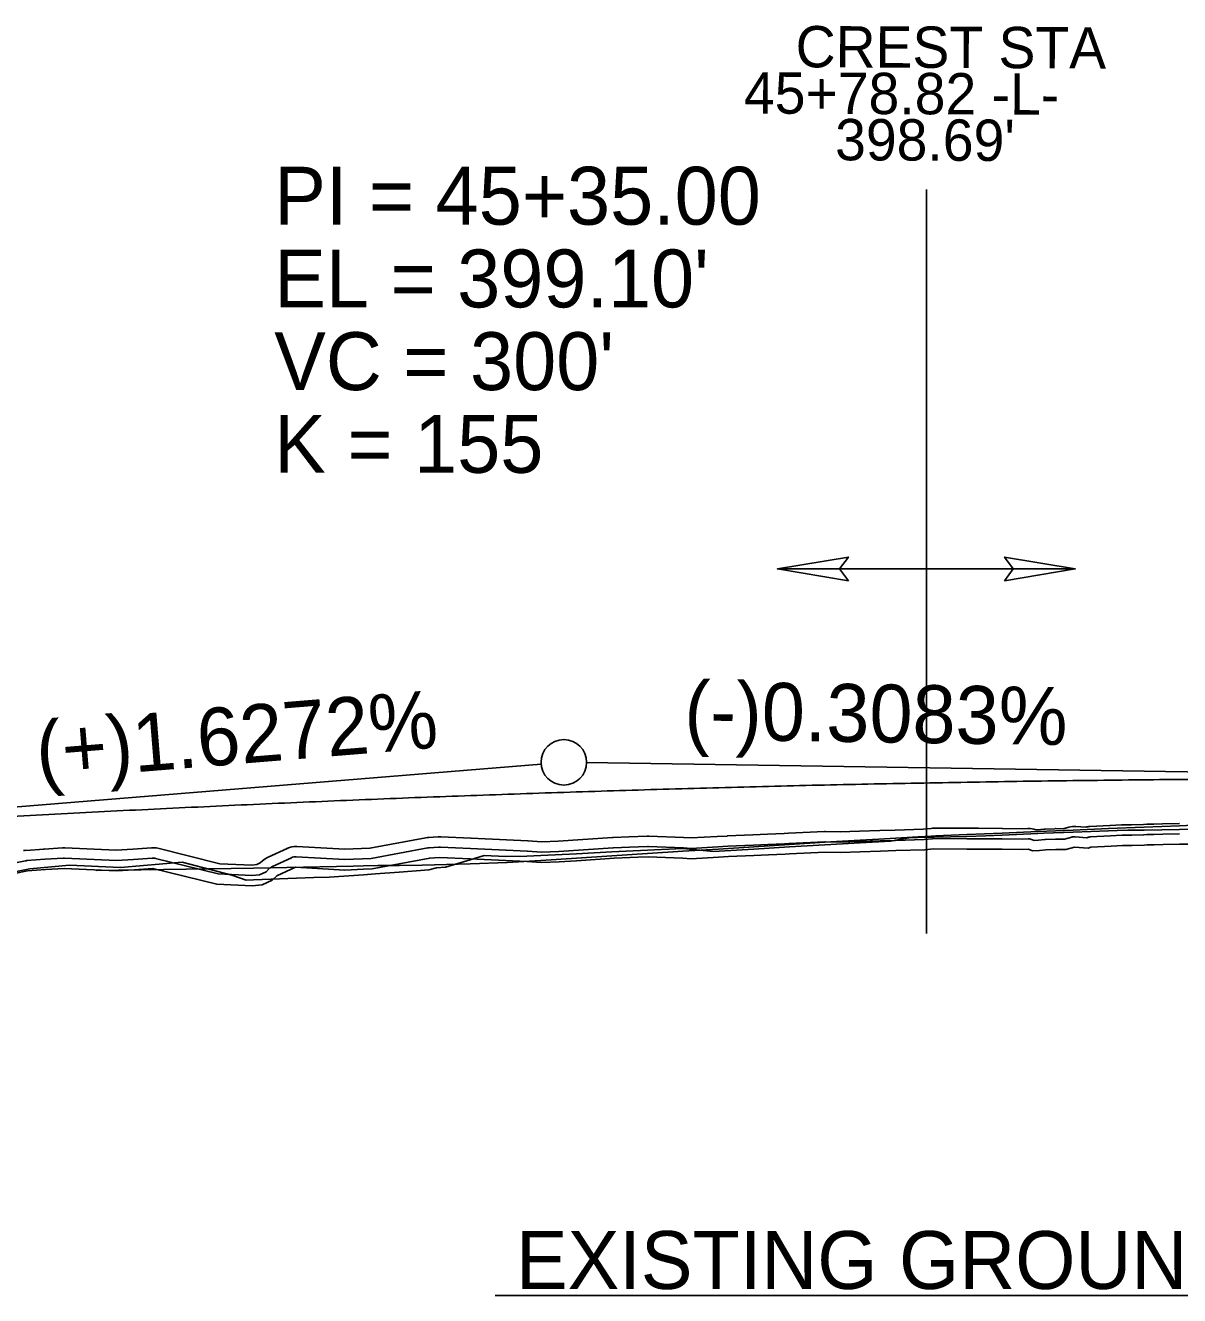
# Model space of a CAD drawing. Extents: x 1625686 to 1640492, y 1161393 to 1175642.
# Drawn here: x 1633674.2 to 1633813.7, y 1175091.8 to 1175245.4 of the extents above; entities that cross this region are included whole.
import ezdxf

# ---------------------------------------------------------------- set-up
doc = ezdxf.new("R2010")
doc.units = 0
for name, color, linetype in [('Exist Vertical Profile Ground Line', 7, 'Continuous'), ('Prop Plan Preparation Crest', 7, 'Continuous'), ('Prop Vertical Profile Curve Label', 7, 'Continuous'), ('Prop Vertical Profile Grade', 7, 'Continuous'), ('Prop Vertical Profile Grade Label', 7, 'Continuous'), ('Prop VPI Label', 7, 'Continuous'), ('Scratch_Level_1', 7, 'Continuous'), ('Scratch_Level_3', 7, 'Continuous'), ('Scratch_Level_5', 7, 'Continuous')]:
    doc.layers.add(name, color=color, linetype=linetype)

msp = doc.modelspace()

# ---------------------------------------------------------------- linework, layer by layer
at = {"layer": 'Exist Vertical Profile Ground Line'}
msp.add_lwpolyline([(1633668.68, 1175142.2), (1633674.79, 1175143.43), (1633679.55, 1175143.87), (1633685.74, 1175143.57), (1633693.17, 1175144.22), (1633699.19, 1175142.67), (1633700.94, 1175142.05), (1633701.8, 1175142.08), (1633709.11, 1175142.39), (1633710.97, 1175142.4), (1633715.12, 1175142.71), (1633716.57, 1175142.82), (1633719.4, 1175143.04), (1633722.98, 1175143.31), (1633723.94, 1175143.53), (1633725.03, 1175143.61), (1633727.98, 1175144.51), (1633729.67, 1175145.02), (1633732.27, 1175144.92), (1633734.85, 1175144.94), (1633736.55, 1175145.03), (1633740.84, 1175145.25), (1633745.13, 1175145.47), (1633749.42, 1175145.69), (1633753.7, 1175145.89), (1633757.4, 1175145.52), (1633758.1, 1175145.56), (1633762.28, 1175145.81), (1633766.57, 1175146.07), (1633770.85, 1175146.32), (1633775.14, 1175146.57), (1633778.78, 1175146.78), (1633779.43, 1175146.89), (1633781.05, 1175147.16), (1633783.05, 1175147.24), (1633783.72, 1175147.23), (1633784.05, 1175147.25), (1633788, 1175147.35), (1633790.3, 1175147.42), (1633792.29, 1175147.51), (1633796.58, 1175147.7), (1633797.33, 1175147.73), (1633800.87, 1175147.87), (1633805.15, 1175148.03), (1633806.18, 1175148.07), (1633807.49, 1175148.08), (1633809.44, 1175148.1), (1633813.73, 1175148.16), (1633818.02, 1175148.21)], dxfattribs=at)
at = {"layer": 'Prop Plan Preparation Crest'}
for p, q in [((1633783.13, 1175135.6), (1633783.13, 1175225.54)), ((1633783.13, 1175179.68), (1633765.13, 1175179.68)), ((1633783.13, 1175179.68), (1633801.13, 1175179.68))]:
    msp.add_line(p, q, dxfattribs=at)
for points in [[(1633773.7, 1175178.26), (1633765.13, 1175179.68), (1633773.7, 1175181.11), (1633772.63, 1175179.68)], [(1633792.57, 1175178.26), (1633801.13, 1175179.68), (1633792.57, 1175181.11), (1633793.63, 1175179.68)]]:
    msp.add_lwpolyline(points, close=True, dxfattribs=at)
at = {"layer": 'Prop Vertical Profile Grade'}
msp.add_spline([(1633589.31, 1175144.1), (1633595.31, 1175144.58), (1633601.31, 1175145.05), (1633607.31, 1175145.51), (1633613.31, 1175145.96), (1633619.31, 1175146.39), (1633625.31, 1175146.82), (1633631.31, 1175147.23), (1633637.31, 1175147.63), (1633643.31, 1175148.02), (1633649.31, 1175148.4), (1633655.31, 1175148.76), (1633661.31, 1175149.12), (1633667.31, 1175149.46), (1633673.31, 1175149.79), (1633679.31, 1175150.11), (1633685.31, 1175150.42), (1633691.31, 1175150.72), (1633697.31, 1175151), (1633703.31, 1175151.28), (1633709.31, 1175151.54), (1633715.31, 1175151.79), (1633721.31, 1175152.03), (1633727.31, 1175152.25), (1633733.31, 1175152.47), (1633739.31, 1175152.67), (1633745.31, 1175152.86), (1633751.31, 1175153.04), (1633757.31, 1175153.21), (1633763.31, 1175153.37), (1633769.31, 1175153.52), (1633775.31, 1175153.65), (1633781.31, 1175153.77), (1633787.31, 1175153.88), (1633793.31, 1175153.98), (1633799.31, 1175154.07), (1633805.31, 1175154.14), (1633811.31, 1175154.21), (1633817.31, 1175154.26), (1633823.31, 1175154.3), (1633829.31, 1175154.33), (1633835.31, 1175154.35), (1633841.31, 1175154.36), (1633847.31, 1175154.35), (1633853.31, 1175154.33), (1633859.31, 1175154.31), (1633865.31, 1175154.27), (1633871.31, 1175154.21), (1633877.31, 1175154.15), (1633883.31, 1175154.07), (1633889.31, 1175153.99)], degree=3, dxfattribs=at)
at = {"layer": 'Prop VPI Label'}
for p, q in [((1633889.31, 1175153.99), (1633742.06, 1175156.26)), ((1633589.31, 1175144.1), (1633736.57, 1175156.08)), ((1633819.62, 1175091.83), (1633731.01, 1175091.83))]:
    msp.add_line(p, q, dxfattribs=at)
msp.add_circle((1633739.31, 1175156.3), 2.75, dxfattribs=at)
at = {"layer": 'Scratch_Level_1'}
for p, q in [((1633801.2, 1175148.54), (1633802.38, 1175148.46)), ((1633802.87, 1175148.53), (1633805.31, 1175148.67)), ((1633805.33, 1175148.67), (1633806.72, 1175148.74)), ((1633809.38, 1175148.8), (1633809.76, 1175148.81)), ((1633809.77, 1175148.81), (1633810.59, 1175148.83)), ((1633724.45, 1175147.3), (1633728.1, 1175147.12)), ((1633728.1, 1175147.12), (1633732.39, 1175146.92)), ((1633732.39, 1175146.92), (1633734.96, 1175146.79)), ((1633749.6, 1175147.38), (1633753.82, 1175147.2)), ((1633757.86, 1175147.33), (1633759.07, 1175147.39)), ((1633759.1, 1175147.4), (1633762.17, 1175147.53)), ((1633765.95, 1175147.71), (1633766.46, 1175147.73)), ((1633766.46, 1175147.73), (1633770.8, 1175147.92)), ((1633775.06, 1175147.98), (1633777.5, 1175148.06)), ((1633777.52, 1175148.06), (1633779.36, 1175148.11)), ((1633783.99, 1175147.08), (1633788, 1175147.07)), ((1633784, 1175148.33), (1633788.01, 1175148.32)), ((1633788, 1175147.07), (1633789.4, 1175147.07)), ((1633788.01, 1175148.32), (1633789.4, 1175148.32)), ((1633789.41, 1175147.07), (1633792.3, 1175147.04)), ((1633789.43, 1175148.32), (1633792.32, 1175148.29)), ((1633797.48, 1175148.23), (1633798.67, 1175148.27)), ((1633797.52, 1175146.98), (1633798.72, 1175147.03)), ((1633802.94, 1175147.29), (1633805.38, 1175147.42)), ((1633805.39, 1175147.42), (1633806.78, 1175147.49)), ((1633809.41, 1175147.55), (1633809.79, 1175147.56)), ((1633809.8, 1175147.56), (1633810.62, 1175147.58)), ((1633674.31, 1175145.66), (1633676.49, 1175145.82)), ((1633676.51, 1175145.82), (1633678.74, 1175145.97)), ((1633703.58, 1175144.85), (1633705.86, 1175145.9)), ((1633724.39, 1175146.05), (1633728.04, 1175145.88)), ((1633728.04, 1175145.88), (1633732.33, 1175145.67)), ((1633732.33, 1175145.67), (1633734.9, 1175145.54)), ((1633749.54, 1175146.14), (1633753.76, 1175145.95)), ((1633757.92, 1175146.08), (1633759.13, 1175146.15)), ((1633759.15, 1175146.15), (1633762.23, 1175146.28)), ((1633766.01, 1175146.46), (1633766.51, 1175146.48)), ((1633766.51, 1175146.48), (1633770.85, 1175146.67)), ((1633775.1, 1175146.73), (1633777.54, 1175146.81)), ((1633777.55, 1175146.81), (1633779.39, 1175146.86)), ((1633674.4, 1175144.42), (1633676.58, 1175144.58)), ((1633676.59, 1175144.58), (1633678.83, 1175144.72)), ((1633704.11, 1175143.72), (1633706.38, 1175144.77))]:
    msp.add_line(p, q, dxfattribs=at)
for points in [[(1633798.79, 1175148.28), (1633799.67, 1175148.27), (1633800.35, 1175148.45)], [(1633806.79, 1175148.74), (1633807.92, 1175148.76), (1633809.38, 1175148.8)], [(1633810.6, 1175148.83), (1633811.68, 1175148.85), (1633813.67, 1175148.89)], [(1633707.05, 1175146.13), (1633712.85, 1175145.79), (1633715.87, 1175145.92), (1633722.65, 1175147.18)], [(1633722.99, 1175147.22), (1633723.52, 1175147.24), (1633724.12, 1175147.29)], [(1633734.98, 1175146.79), (1633736.65, 1175146.7), (1633738.63, 1175146.77), (1633745.21, 1175147.21)], [(1633745.28, 1175147.21), (1633747.18, 1175147.29), (1633749.38, 1175147.38)], [(1633753.82, 1175147.2), (1633754.69, 1175147.16), (1633757.85, 1175147.33)], [(1633762.17, 1175147.53), (1633763.91, 1175147.6), (1633765.93, 1175147.71)], [(1633770.94, 1175147.92), (1633772.71, 1175147.9), (1633775.06, 1175147.98)], [(1633779.36, 1175148.11), (1633782.76, 1175148.21), (1633783.72, 1175148.31)], [(1633779.39, 1175146.86), (1633782.85, 1175146.96), (1633783.86, 1175147.07)], [(1633792.3, 1175147.04), (1633794.71, 1175147.02), (1633795.45, 1175147.04)], [(1633792.32, 1175148.29), (1633794.7, 1175148.27), (1633795.4, 1175148.29)], [(1633795.97, 1175146.94), (1633796.16, 1175146.86), (1633796.68, 1175146.9), (1633797.44, 1175146.98)], [(1633796.36, 1175148.13), (1633796.57, 1175148.15), (1633797.32, 1175148.22)], [(1633798.77, 1175147.03), (1633799.84, 1175147.01), (1633800.69, 1175147.25)], [(1633801.11, 1175147.29), (1633802.52, 1175147.19), (1633802.64, 1175147.23)], [(1633806.81, 1175147.49), (1633807.95, 1175147.51), (1633809.41, 1175147.55)], [(1633810.62, 1175147.58), (1633811.71, 1175147.6), (1633813.7, 1175147.64)], [(1633679.02, 1175145.97), (1633685.23, 1175145.69), (1633687.23, 1175145.82), (1633689.47, 1175145.97)], [(1633690.25, 1175145.91), (1633697.73, 1175144.04), (1633701.59, 1175143.88), (1633702.21, 1175143.93), (1633702.62, 1175144.13), (1633702.9, 1175144.39)], [(1633706.98, 1175144.88), (1633712.84, 1175144.54), (1633716.01, 1175144.68), (1633722.88, 1175145.95)], [(1633723.05, 1175145.97), (1633723.61, 1175146), (1633724.23, 1175146.05)], [(1633734.91, 1175145.54), (1633736.63, 1175145.44), (1633738.7, 1175145.52), (1633745.29, 1175145.96)], [(1633745.33, 1175145.96), (1633747.24, 1175146.04), (1633749.43, 1175146.14)], [(1633753.76, 1175145.95), (1633754.69, 1175145.9), (1633757.92, 1175146.08)], [(1633762.23, 1175146.28), (1633763.97, 1175146.35), (1633766, 1175146.46)], [(1633770.93, 1175146.67), (1633772.72, 1175146.65), (1633775.1, 1175146.73)], [(1633659.73, 1175142.7), (1633665.85, 1175143.01), (1633668.02, 1175143.13), (1633674.24, 1175144.39)], [(1633678.97, 1175144.72), (1633685.24, 1175144.44), (1633687.31, 1175144.57), (1633689.56, 1175144.73)], [(1633689.95, 1175144.69), (1633697.55, 1175142.8), (1633701.61, 1175142.63), (1633702.53, 1175142.7), (1633703.34, 1175143.08), (1633703.76, 1175143.49)]]:
    msp.add_lwpolyline(points, dxfattribs=at)
for centre, radius, start, end in [((1633801.02, 1175146.05), 2.5, 85.9806, 105.5959), ((1633803.01, 1175146.04), 2.5, 93.1907, 104.5413), ((1633805.45, 1175146.17), 2.5, 92.7647, 93.1907), ((1633806.84, 1175146.24), 2.5, 91.1256, 92.7647), ((1633809.44, 1175146.3), 2.5, 91.4585, 91.4846), ((1633809.83, 1175146.31), 2.5, 91.3484, 91.4585), ((1633810.65, 1175146.33), 2.5, 90.9329, 91.3484), ((1633813.73, 1175146.39), 2.5, 89.9004, 91.3294), ((1633723.11, 1175144.72), 2.5, 92.7649, 100.4912), ((1633724.33, 1175144.8), 2.5, 87.2388, 94.9283), ((1633727.98, 1175144.63), 2.5, 87.2354, 87.2388), ((1633732.27, 1175144.42), 2.5, 87.2321, 87.2354), ((1633745.38, 1175144.71), 2.5, 92.2481, 93.8382), ((1633749.49, 1175144.89), 2.5, 87.421, 92.5346), ((1633753.7, 1175144.7), 2.5, 87.4111, 87.421), ((1633757.99, 1175144.83), 2.5, 93.1155, 93.128), ((1633759.2, 1175144.9), 2.5, 92.4381, 93.1155), ((1633762.28, 1175145.03), 2.5, 92.4254, 92.4381), ((1633766.06, 1175145.21), 2.5, 92.5421, 93.023), ((1633766.57, 1175145.23), 2.5, 92.53, 92.5421), ((1633770.91, 1175145.43), 2.5, 89.1847, 92.53), ((1633775.14, 1175145.48), 2.5, 91.9474, 91.9636), ((1633777.59, 1175145.56), 2.5, 91.5664, 91.9474), ((1633779.43, 1175145.62), 2.5, 91.5501, 91.5664), ((1633783.99, 1175145.83), 2.5, 89.9405, 96.2914), ((1633783.99, 1175145.83), 1.25, 89.9405, 96.2914), ((1633788, 1175145.82), 1.25, 89.9331, 89.9405), ((1633788, 1175145.82), 2.5, 89.9331, 89.9405), ((1633789.4, 1175145.82), 2.5, 89.4016, 89.9331), ((1633789.4, 1175145.82), 1.25, 89.4016, 89.9331), ((1633792.29, 1175145.79), 1.25, 89.394, 89.4016), ((1633792.29, 1175145.79), 2.5, 89.394, 89.4016), ((1633795.49, 1175145.79), 2.5, 69.4483, 91.8684), ((1633795.49, 1175145.79), 1.25, 66.9741, 91.8684), ((1633797.57, 1175145.73), 2.5, 91.9853, 95.7529), ((1633797.57, 1175145.73), 1.25, 91.9853, 95.7529), ((1633798.76, 1175145.78), 2.5, 89.3174, 91.9853), ((1633798.76, 1175145.78), 1.25, 89.3174, 91.9853), ((1633801.02, 1175146.05), 1.25, 85.9806, 105.5959), ((1633803.01, 1175146.04), 1.25, 93.1907, 107.416), ((1633805.45, 1175146.17), 1.25, 92.7647, 93.1907), ((1633806.84, 1175146.24), 1.25, 91.1256, 92.7647), ((1633809.44, 1175146.3), 1.25, 91.4585, 91.4846), ((1633809.83, 1175146.31), 1.25, 91.3484, 91.4585), ((1633810.65, 1175146.33), 1.25, 90.9329, 91.3484), ((1633813.73, 1175146.39), 1.25, 89.9004, 91.3294), ((1633674.49, 1175143.17), 2.5, 94.1965, 101.4805), ((1633676.67, 1175143.33), 2.5, 93.7655, 94.1965), ((1633678.91, 1175143.48), 2.5, 87.3911, 93.7655), ((1633689.65, 1175143.48), 2.5, 76.0153, 93.9476), ((1633706.9, 1175143.63), 2.5, 86.6248, 114.7526), ((1633723.11, 1175144.72), 1.25, 92.7649, 100.4912), ((1633724.33, 1175144.8), 1.25, 87.2388, 94.9283), ((1633727.98, 1175144.63), 1.25, 87.2354, 87.2388), ((1633732.27, 1175144.42), 1.25, 87.2321, 87.2354), ((1633734.84, 1175144.3), 1.25, 86.689, 87.2321), ((1633734.84, 1175144.3), 2.5, 86.689, 87.2321), ((1633745.38, 1175144.71), 1.25, 92.2481, 93.8382), ((1633749.49, 1175144.89), 1.25, 87.421, 92.5346), ((1633753.7, 1175144.7), 1.25, 87.4111, 87.421), ((1633757.99, 1175144.83), 1.25, 93.1155, 93.128), ((1633759.2, 1175144.9), 1.25, 92.4381, 93.1155), ((1633762.28, 1175145.03), 1.25, 92.4254, 92.4381), ((1633766.06, 1175145.21), 1.25, 92.5421, 93.023), ((1633766.57, 1175145.23), 1.25, 92.53, 92.5421), ((1633770.91, 1175145.43), 1.25, 89.1847, 92.53), ((1633775.14, 1175145.48), 1.25, 91.9474, 91.9636), ((1633777.59, 1175145.56), 1.25, 91.5664, 91.9474), ((1633779.43, 1175145.62), 1.25, 91.5501, 91.5664), ((1633674.49, 1175143.17), 1.25, 94.1965, 101.4805), ((1633676.67, 1175143.33), 1.25, 93.7655, 94.1965), ((1633678.91, 1175143.48), 1.25, 87.3911, 93.7655), ((1633689.65, 1175143.48), 1.25, 76.0153, 93.9476), ((1633704.63, 1175142.58), 2.5, 114.7526, 133.7236), ((1633706.9, 1175143.63), 1.25, 86.6248, 114.7526), ((1633704.63, 1175142.58), 1.25, 114.7526, 133.7236)]:
    msp.add_arc(centre, radius, start, end, dxfattribs=at)
at = {"layer": 'Scratch_Level_3'}
msp.add_lwpolyline([(1633682.78, 1175143.23), (1633701.8, 1175143.5), (1633713.87, 1175143.76), (1633715.12, 1175143.79), (1633716.83, 1175143.83), (1633719.4, 1175143.84), (1633722.21, 1175143.85), (1633723.69, 1175143.9), (1633727.98, 1175144.04), (1633732.48, 1175144.19), (1633736.55, 1175144.45), (1633740.84, 1175144.72), (1633745.13, 1175145), (1633749.42, 1175145.27), (1633753.7, 1175145.54), (1633757.99, 1175145.82), (1633762.28, 1175146.09), (1633766.57, 1175146.36), (1633770.85, 1175146.63), (1633775.14, 1175146.89), (1633777.39, 1175147.03), (1633779.43, 1175147.14), (1633782.12, 1175147.29), (1633783.72, 1175147.38), (1633784.26, 1175147.41), (1633788, 1175147.57), (1633792.29, 1175147.75), (1633796.58, 1175147.93), (1633800.87, 1175148.11), (1633805.15, 1175148.29), (1633809.44, 1175148.47), (1633813.73, 1175148.64), (1633818.02, 1175148.81)], dxfattribs=at)
at = {"layer": 'Scratch_Level_5'}
msp.add_lwpolyline([(1633668.18, 1175141.89), (1633674.49, 1175143.17), (1633676.67, 1175143.33), (1633678.91, 1175143.48), (1633685.25, 1175143.19), (1633687.4, 1175143.32), (1633689.65, 1175143.48), (1633697.37, 1175141.56), (1633701.63, 1175141.38), (1633702.85, 1175141.47), (1633704.06, 1175142.04), (1633704.63, 1175142.58), (1633706.9, 1175143.63), (1633712.83, 1175143.28), (1633715.12, 1175143.39), (1633716.15, 1175143.43), (1633719.4, 1175144.03), (1633723.11, 1175144.72), (1633723.69, 1175144.75), (1633724.33, 1175144.8), (1633727.98, 1175144.63), (1633732.27, 1175144.42), (1633734.84, 1175144.3), (1633736.62, 1175144.19), (1633738.76, 1175144.27), (1633740.84, 1175144.41), (1633745.38, 1175144.71), (1633747.29, 1175144.79), (1633748.24, 1175144.83), (1633749.49, 1175144.89), (1633753.7, 1175144.7), (1633754.7, 1175144.65), (1633757.99, 1175144.83), (1633759.2, 1175144.9), (1633762.28, 1175145.03), (1633764.03, 1175145.1), (1633766.06, 1175145.21), (1633766.57, 1175145.23), (1633770.91, 1175145.43), (1633772.73, 1175145.4), (1633775.14, 1175145.48), (1633777.59, 1175145.56), (1633779.43, 1175145.62), (1633782.93, 1175145.71), (1633783.99, 1175145.83), (1633788, 1175145.82), (1633789.4, 1175145.82), (1633792.29, 1175145.79), (1633794.73, 1175145.77), (1633795.49, 1175145.79), (1633795.95, 1175145.59), (1633796.79, 1175145.66), (1633797.57, 1175145.73), (1633798.76, 1175145.78), (1633800, 1175145.76), (1633801.02, 1175146.05), (1633802.67, 1175145.93), (1633803.01, 1175146.04), (1633805.45, 1175146.17), (1633806.84, 1175146.24), (1633807.98, 1175146.26), (1633809.44, 1175146.3), (1633809.83, 1175146.31), (1633810.65, 1175146.33), (1633811.73, 1175146.35), (1633813.73, 1175146.39), (1633815.93, 1175146.39)], dxfattribs=at)

# ---------------------------------------------------------------- texts
at = {"layer": 'Prop Plan Preparation Crest'}
for s, p in [('CREST STA', (1633767.32, 1175240.33)), ('45+78.82 -L-', (1633761.07, 1175234.74)), ("398.69'", (1633772.09, 1175229.09))]:
    msp.add_text(s, height=5, rotation=359.7547, dxfattribs=at).set_placement(p)
at = {"layer": 'Prop Vertical Profile Curve Label'}
for s, p in [("VC = 300'", (1633704.31, 1175201.3)), ('K = 155', (1633704.31, 1175191.3))]:
    msp.add_text(s, height=7, dxfattribs=at).set_placement(p)
at = {"layer": 'Prop Vertical Profile Grade Label'}
for s, rotation, p in [('(-)0.3083%', 359.1169, (1633753.84, 1175159.08)), ('(+)1.6272%', 4.6514, (1633675.8, 1175154.14)), ('(+)1.6272%', 4.6514, (1633675.8, 1175154.14))]:
    msp.add_text(s, height=7, rotation=rotation, dxfattribs=at).set_placement(p)
at = {"layer": 'Prop VPI Label'}
for s, p in [('PI = 45+35.00', (1633704.31, 1175221.3)), ("EL = 399.10'", (1633704.31, 1175211.3)), ('EXISTING GROUND', (1633733.53, 1175092.63))]:
    msp.add_text(s, height=7, dxfattribs=at).set_placement(p)

doc.saveas('drawing.dxf')
